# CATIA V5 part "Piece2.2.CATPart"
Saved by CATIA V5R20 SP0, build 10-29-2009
Part number: Piece2.2
Bounding box of the stored display mesh (mm): x 0 to 100, y 228.37 to 259.019, z 111.247 to 298.759
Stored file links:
  C:\Users\Lambert\Desktop\IAO\Piece2.2.CATPart
  C:\Users\Lambert\Desktop\IAO\Produit1.CATProduct
  C:\Users\Lambert\Desktop\IAO\skl_general.CATPart
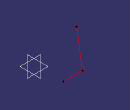
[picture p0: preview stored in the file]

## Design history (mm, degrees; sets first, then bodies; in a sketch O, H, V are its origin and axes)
Set1
  DatumPoint1 "C": linked copy from another document
  DatumPoint2 "E": linked copy from another document
  Plane1 "Plan_Ref": linked copy from another document
Set2
  Line1 "Bielle 2.2": type PtPt, FirstPoint DatumPoint1, SecondPoint DatumPoint2, Support Plane1
  Line2 "Axe_pivot_52": type Normal, RefPoint DatumPoint1, RefSkin Plane1, Start 0, End 100
Body1 (main body)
